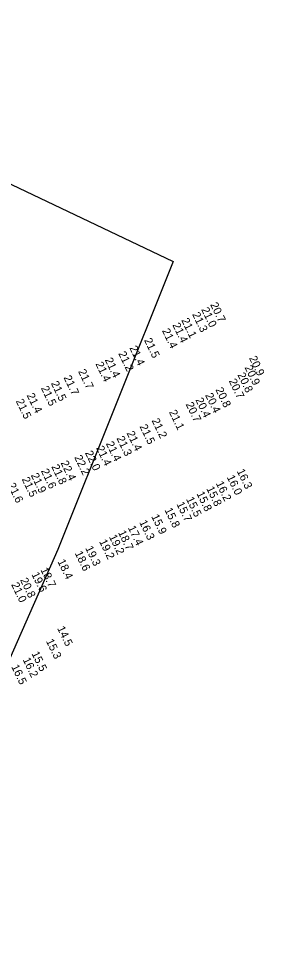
# Model space of a CAD drawing. Extents: x 507575 to 511975, y 1309304 to 1312704.
# Drawn here: x 509066 to 509373, y 1310376 to 1311537 of the extents above; entities that cross this region are included whole.
import ezdxf

# ---------------------------------------------------------------- set-up
doc = ezdxf.new("R2010")
doc.units = 0
doc.layers.add('C-CHAN-TBAS', color=7, linetype='Continuous')
doc.layers.add('V-TOPO-SOUN', color=7, linetype='Continuous')

msp = doc.modelspace()

# ---------------------------------------------------------------- linework, layer by layer
at = {"layer": 'C-CHAN-TBAS'}
for p, q in [((508620.4, 1311537.1), (509259.4, 1311233.7)), ((509259.4, 1311233.7), (509115, 1310874.1)), ((509115, 1310874.1), (508884.6, 1310352.7))]:
    msp.add_line(p, q, dxfattribs=at)

# ---------------------------------------------------------------- texts
at = {"layer": 'V-TOPO-SOUN'}
for s, p in [('21.0 ', (509294.2, 1311174)), ('20.7 ', (509305.4, 1311180.1)), ('21.3 ', (509282.9, 1311167.9)), ('21.4 ', (509258.2, 1311154.6)), ('21.1 ', (509269.3, 1311160.6)), ('21.4 ', (509245.2, 1311147.5)), ('21.5 ', (509222.8, 1311135.6)), ('21.2 ', (509190.5, 1311119)), ('21.4 ', (509204.4, 1311126.1)), ('21.4 ', (509162, 1311105.9)), ('21.4 ', (509173.7, 1311111.1)), ('20.9 ', (509354, 1311113.3)), ('21.7 ', (509140.3, 1311096.7)), ('20.8 ', (509339.5, 1311092.5)), ('20.9 ', (509348.4, 1311101.6)), ('21.5 ', (509106.3, 1311081.8)), ('21.7 ', (509122.1, 1311089)), ('20.7 ', (509328.7, 1311084.7)), ('21.5 ', (509093.8, 1311075.8)), ('20.8 ', (509312, 1311073.9)), ('21.5 ', (509062.4, 1311059.6)), ('21.4 ', (509076, 1311066.8)), ('20.4 ', (509286.9, 1311061.2)), ('20.4 ', (509299.1, 1311067)), ('21.1 ', (509253.9, 1311045.9)), ('20.7 ', (509274.8, 1311055.6)), ('21.2 ', (509232.2, 1311035.4)), ('21.5 ', (509217.1, 1311027.9)), ('21.3 ', (509188.3, 1311013.2)), ('21.4 ', (509200.9, 1311019.6)), ('21.4 ', (509162.8, 1311001)), ('21.4 ', (509175, 1311006.6)), ('22.2 ', (509135.5, 1310989.4)), ('22.0 ', (509148.9, 1310995)), ('21.8 ', (509106.8, 1310977.8)), ('22.4 ', (509118.4, 1310982.5)), ('21.9 ', (509081.2, 1310967)), ('21.6 ', (509093.8, 1310972.4)), ('16.0 ', (509326.2, 1310964.6)), ('16.3 ', (509338.7, 1310972.2)), ('21.6 ', (509052.2, 1310954.8)), ('21.5 ', (509069.8, 1310962.1)), ('16.2 ', (509312.5, 1310956.9)), ('15.8 ', (509288.3, 1310944.1)), ('15.8 ', (509300.6, 1310950.5)), ('15.7 ', (509263.2, 1310931.2)), ('15.5 ', (509275.3, 1310937.3)), ('15.8 ', (509248.3, 1310923.7)), ('16.3 ', (509216.7, 1310908.4)), ('15.9 ', (509231.8, 1310915.6)), ('18.7 ', (509190.2, 1310895.6)), ('17.4 ', (509202.5, 1310901.5)), ('19.2 ', (509166.6, 1310884.3)), ('19.2 ', (509178.9, 1310890.2)), ('19.3 ', (509149.2, 1310876)), ('18.6 ', (509136.1, 1310869.7)), ('18.7 ', (509093.2, 1310849.1)), ('18.4 ', (509114.5, 1310859.4)), ('20.8 ', (509067.8, 1310836.2)), ('19.6 ', (509081.9, 1310843.4)), ('21.0 ', (509056.6, 1310830.5)), ('14.5 ', (509114.1, 1310775.9)), ('15.3 ', (509100.1, 1310760)), ('15.5 ', (509082, 1310744.4)), ('16.2 ', (509071, 1310736.8)), ('16.5 ', (509056.7, 1310728))]:
    msp.add_text(s, height=10, rotation=295.6464, dxfattribs=at).set_placement(p)

doc.saveas('drawing.dxf')
